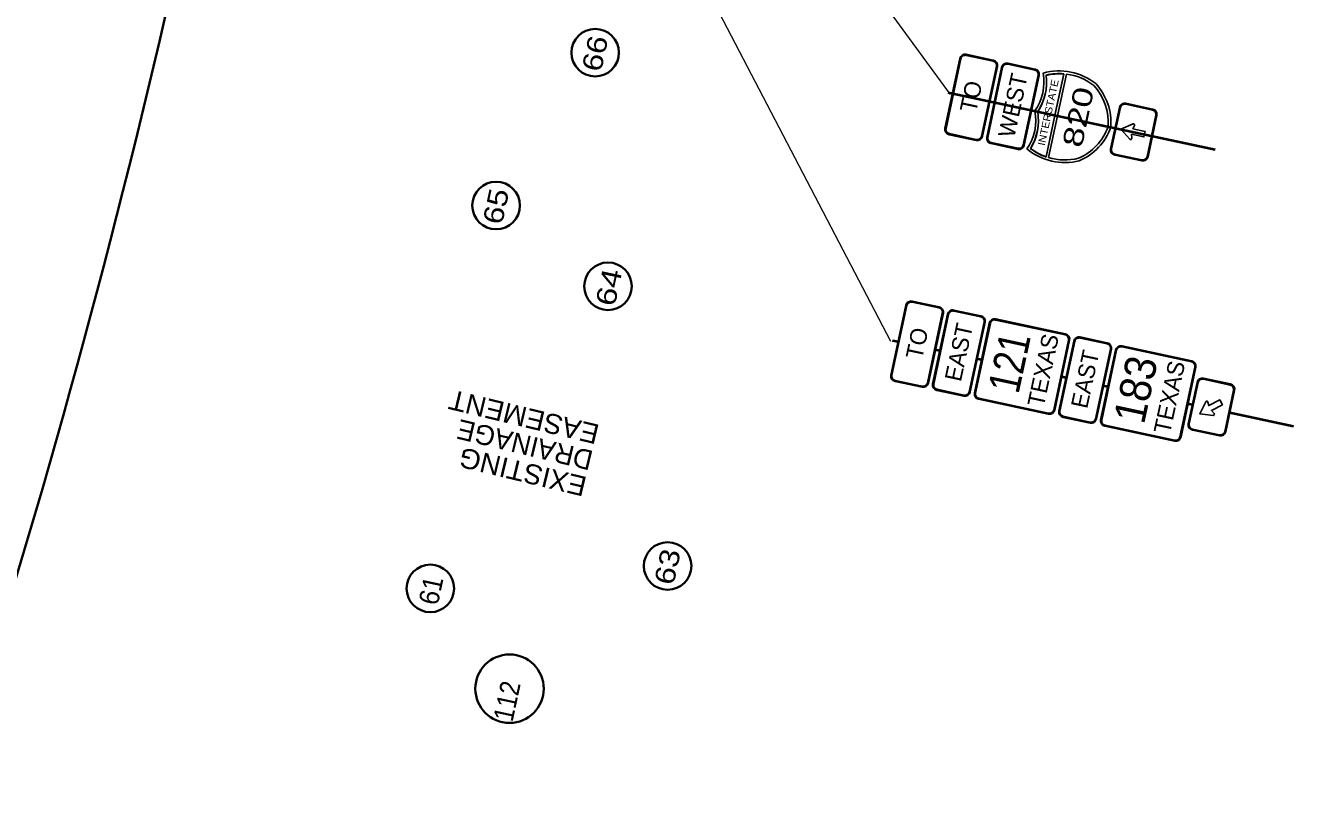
# Model space of a CAD drawing. Extents: x 2363411 to 2369702, y 6977197 to 6988655.
# Drawn here: x 2366110 to 2367007, y 6983011 to 6983553 of the extents above; entities that cross this region are included whole.
import ezdxf
from ezdxf.enums import TextEntityAlignment as Align

# ---------------------------------------------------------------- set-up
doc = ezdxf.new("R2010")
doc.units = 0
doc.header["$LTSCALE"] = 5.6
for name, color, linetype, lineweight in [('1', 7, 'Continuous', 25), ('17', 7, 'Continuous', 35), ('48', 7, 'Continuous', 25), ('55', 7, 'Continuous', 35)]:
    doc.layers.add(name, color=color, linetype=linetype, lineweight=lineweight)

msp = doc.modelspace()

# ---------------------------------------------------------------- linework, layer by layer
at = {"layer": '1', "lineweight": 13}
for p, q in [((2366432.524, 6983885.673), (2366722.178, 6983330.158)), ((2366489.804, 6983881.732), (2366764.313, 6983504.552))]:
    msp.add_line(p, q, dxfattribs=at)
at = {"layer": '1'}
for p, q in [((2366844.762, 6983519.251), (2366838.496, 6983489.913)), ((2366846.653, 6983519.04), (2366840.344, 6983489.521)), ((2366832.229, 6983460.577), (2366838.496, 6983489.913)), ((2366834.036, 6983459.977), (2366840.344, 6983489.521)), ((2366832.255, 6983460.372), (2366832.26, 6983460.382))]:
    msp.add_line(p, q, dxfattribs=at)
for points in [[(2366832.26, 6983460.382), (2366838.524, 6983489.72), (2366844.792, 6983519.049)], [(2366846.653, 6983519.042), (2366840.344, 6983489.521), (2366834.037, 6983459.977)]]:
    msp.add_lwpolyline(points, dxfattribs=at)
at = {"layer": '1', "lineweight": 35}
msp.add_arc((2359877.328, 6985028.058), 6500, 337.9611, 358.49155, dxfattribs=at)
at = {"layer": '1'}
for centre, radius, start, end in [((2366794.792, 6983513.514), 35.984, 325.11936, 9.96967), ((2366794.792, 6983513.514), 37.874, 326.31727, 7.31411), ((2366794.821, 6983513.319), 37.876, 326.31755, 7.31439), ((2366841.448, 6983479.316), 41.954, 51.80216, 105.50453), ((2366841.448, 6983479.316), 40.064, 85.2486, 103.11335), ((2366841.478, 6983479.12), 40.066, 85.25606, 103.11363), ((2366841.446, 6983479.316), 40.066, 52.01897, 82.53095), ((2366841.448, 6983479.316), 40.064, 52.01869, 82.53068), ((2366837.454, 6983484.715), 38.81, 355.77729, 42.42367), ((2366837.456, 6983484.715), 38.808, 355.77701, 42.42339), ((2366837.456, 6983484.715), 40.698, 355.41087, 42.64677), ((2366788.96, 6983486.218), 35.984, 325.90827, 10.75858), ((2366788.96, 6983486.218), 37.874, 328.56383, 9.56067), ((2366788.988, 6983486.023), 37.876, 328.56411, 9.56095), ((2366839.666, 6983495.066), 38.81, 293.45483, 340.10121), ((2366839.668, 6983495.066), 38.808, 293.45455, 340.10093), ((2366839.668, 6983495.066), 40.698, 293.23117, 340.46707), ((2366845.517, 6983498.362), 41.954, 230.37341, 284.07578), ((2366845.517, 6983498.362), 40.064, 232.76459, 250.62934), ((2366845.548, 6983498.167), 40.066, 232.76486, 250.62547), ((2366845.517, 6983498.362), 40.064, 253.34726, 283.85925), ((2366845.516, 6983498.363), 40.066, 253.35167, 283.85953)]:
    msp.add_arc(centre, radius, start, end, dxfattribs=at)
at = {"layer": '17'}
for centre, radius in [((2366513.358, 6983534.192), 16.828), ((2366443.307, 6983426.053), 16.828), ((2366522.427, 6983368.915), 16.828), ((2366564.604, 6983171.066), 16.828), ((2366396.799, 6983155.195), 16.828), ((2366452.783, 6983084.265), 24.19)]:
    msp.add_circle(centre, radius, dxfattribs=at)
at = {"layer": '48'}
for p, q in [((2366760.731, 6983480.729), (2366771.271, 6983530.06)), ((2366761.482, 6983480.569), (2366772.022, 6983529.899)), ((2366761.482, 6983480.569), (2366772.022, 6983529.899)), ((2366775.669, 6983532.262), (2366794.751, 6983528.184)), ((2366775.669, 6983532.262), (2366794.751, 6983528.184)), ((2366775.829, 6983533.013), (2366794.912, 6983528.935)), ((2366805.196, 6983525.953), (2366824.278, 6983521.875)), ((2366805.196, 6983525.953), (2366824.278, 6983521.875)), ((2366805.356, 6983526.704), (2366824.439, 6983522.626)), ((2366797.114, 6983524.538), (2366786.573, 6983475.207)), ((2366797.114, 6983524.538), (2366786.573, 6983475.207)), ((2366797.865, 6983524.378), (2366787.324, 6983475.047)), ((2366790.258, 6983474.42), (2366800.798, 6983523.751)), ((2366791.009, 6983474.26), (2366801.549, 6983523.59)), ((2366791.009, 6983474.26), (2366801.549, 6983523.59)), ((2366826.641, 6983518.229), (2366816.1, 6983468.898)), ((2366826.641, 6983518.229), (2366816.1, 6983468.898)), ((2366827.392, 6983518.069), (2366816.851, 6983468.738)), ((2366877.835, 6983466.219), (2366884.08, 6983495.445)), ((2366878.586, 6983466.058), (2366884.831, 6983495.284)), ((2366878.586, 6983466.058), (2366884.831, 6983495.284)), ((2366888.477, 6983497.647), (2366907.56, 6983493.569)), ((2366888.477, 6983497.647), (2366907.56, 6983493.569)), ((2366888.637, 6983498.398), (2366907.72, 6983494.32)), ((2366909.922, 6983489.923), (2366903.677, 6983460.697)), ((2366909.922, 6983489.923), (2366903.677, 6983460.697)), ((2366910.673, 6983489.763), (2366904.428, 6983460.537)), ((2366782.767, 6983472.094), (2366763.684, 6983476.171)), ((2366782.927, 6983472.845), (2366763.844, 6983476.922)), ((2366782.927, 6983472.845), (2366763.844, 6983476.922)), ((2366812.294, 6983465.785), (2366793.211, 6983469.862)), ((2366812.454, 6983466.536), (2366793.371, 6983470.613)), ((2366812.454, 6983466.536), (2366793.371, 6983470.613)), ((2366899.871, 6983457.584), (2366880.788, 6983461.661)), ((2366900.031, 6983458.335), (2366880.948, 6983462.412)), ((2366900.031, 6983458.335), (2366880.948, 6983462.412)), ((2366722.5, 6983306.15), (2366733.04, 6983355.481)), ((2366723.251, 6983305.99), (2366733.791, 6983355.32)), ((2366723.251, 6983305.99), (2366733.791, 6983355.32)), ((2366737.437, 6983357.683), (2366756.52, 6983353.605)), ((2366737.437, 6983357.683), (2366756.52, 6983353.605)), ((2366737.598, 6983358.434), (2366756.681, 6983354.356)), ((2366758.882, 6983349.959), (2366748.342, 6983300.628)), ((2366758.882, 6983349.959), (2366748.342, 6983300.628)), ((2366759.634, 6983349.799), (2366749.093, 6983300.468)), ((2366752.027, 6983299.841), (2366762.567, 6983349.172)), ((2366752.778, 6983299.681), (2366763.318, 6983349.011)), ((2366752.778, 6983299.681), (2366763.318, 6983349.011)), ((2366766.964, 6983351.374), (2366786.047, 6983347.296)), ((2366766.964, 6983351.374), (2366786.047, 6983347.296)), ((2366767.125, 6983352.125), (2366786.208, 6983348.047)), ((2366788.409, 6983343.65), (2366777.869, 6983294.319)), ((2366788.409, 6983343.65), (2366777.869, 6983294.319)), ((2366789.161, 6983343.49), (2366778.62, 6983294.159)), ((2366781.554, 6983293.532), (2366792.094, 6983342.863)), ((2366782.305, 6983293.372), (2366792.845, 6983342.702)), ((2366782.305, 6983293.372), (2366792.845, 6983342.702)), ((2366796.491, 6983345.065), (2366845.822, 6983334.524)), ((2366796.491, 6983345.065), (2366845.822, 6983334.524)), ((2366796.652, 6983345.816), (2366845.983, 6983335.275)), ((2366848.184, 6983330.878), (2366837.644, 6983281.547)), ((2366848.184, 6983330.878), (2366837.644, 6983281.547)), ((2366848.935, 6983330.718), (2366838.395, 6983281.387)), ((2366841.329, 6983280.76), (2366851.869, 6983330.091)), ((2366842.08, 6983280.6), (2366852.62, 6983329.93)), ((2366842.08, 6983280.6), (2366852.62, 6983329.93)), ((2366856.266, 6983332.293), (2366875.349, 6983328.215)), ((2366856.266, 6983332.293), (2366875.349, 6983328.215)), ((2366856.427, 6983333.044), (2366875.51, 6983328.966)), ((2366877.711, 6983324.569), (2366867.171, 6983275.238)), ((2366877.711, 6983324.569), (2366867.171, 6983275.238)), ((2366878.462, 6983324.409), (2366867.922, 6983275.078)), ((2366870.856, 6983274.451), (2366881.396, 6983323.782)), ((2366871.607, 6983274.291), (2366882.147, 6983323.621)), ((2366871.607, 6983274.291), (2366882.147, 6983323.621)), ((2366885.793, 6983325.984), (2366935.124, 6983315.443)), ((2366885.793, 6983325.984), (2366935.124, 6983315.443)), ((2366885.954, 6983326.735), (2366935.284, 6983316.194)), ((2366937.486, 6983311.797), (2366926.946, 6983262.466)), ((2366937.486, 6983311.797), (2366926.946, 6983262.466)), ((2366938.237, 6983311.637), (2366927.697, 6983262.306)), ((2366744.535, 6983297.515), (2366725.453, 6983301.593)), ((2366744.696, 6983298.266), (2366725.613, 6983302.344)), ((2366744.696, 6983298.266), (2366725.613, 6983302.344)), ((2366943.42, 6983303.159), (2366962.503, 6983299.082)), ((2366943.42, 6983303.159), (2366962.503, 6983299.082)), ((2366943.581, 6983303.91), (2366962.664, 6983299.833)), ((2366774.062, 6983291.206), (2366754.98, 6983295.284)), ((2366774.223, 6983291.957), (2366755.14, 6983296.035)), ((2366774.223, 6983291.957), (2366755.14, 6983296.035)), ((2366932.779, 6983271.732), (2366939.023, 6983300.957)), ((2366933.53, 6983271.571), (2366939.774, 6983300.797)), ((2366933.53, 6983271.571), (2366939.774, 6983300.797)), ((2366964.865, 6983295.436), (2366958.621, 6983266.21)), ((2366964.865, 6983295.436), (2366958.621, 6983266.21)), ((2366965.616, 6983295.275), (2366959.372, 6983266.049)), ((2366833.837, 6983278.434), (2366784.507, 6983288.975)), ((2366833.998, 6983279.185), (2366784.667, 6983289.726)), ((2366833.998, 6983279.185), (2366784.667, 6983289.726)), ((2366863.364, 6983272.125), (2366844.282, 6983276.203)), ((2366863.525, 6983272.876), (2366844.442, 6983276.954)), ((2366863.525, 6983272.876), (2366844.442, 6983276.954)), ((2366923.139, 6983259.353), (2366873.809, 6983269.894)), ((2366923.3, 6983260.104), (2366873.969, 6983270.645)), ((2366923.3, 6983260.104), (2366873.969, 6983270.645)), ((2366954.814, 6983263.097), (2366935.731, 6983267.174)), ((2366954.975, 6983263.848), (2366935.892, 6983267.925)), ((2366954.975, 6983263.848), (2366935.892, 6983267.925))]:
    msp.add_line(p, q, dxfattribs=at)
at = {"layer": '48', "lineweight": 40}
for p, q in [((2366762.962, 6983506.044), (2366951.956, 6983465.662)), ((2366723.531, 6983330.659), (2366727.603, 6983329.789)), ((2366753.909, 6983324.168), (2366757.015, 6983323.504)), ((2366783.321, 6983317.883), (2366786.427, 6983317.22)), ((2366843.3, 6983305.068), (2366846.211, 6983304.446)), ((2366872.743, 6983298.777), (2366875.752, 6983298.134)), ((2366932.555, 6983285.997), (2366935.661, 6983285.333)), ((2366962.257, 6983279.65), (2367007.333, 6983270.019))]:
    msp.add_line(p, q, dxfattribs=at)
at = {"layer": '48'}
for points in [[(2366891.562, 6983473.044), (2366885.078, 6983480.025), (2366893.771, 6983483.726)], [(2366894.762, 6983482.681), (2366893.619, 6983480.372), (2366902.273, 6983478.523), (2366901.429, 6983474.567), (2366892.774, 6983476.417), (2366892.906, 6983473.592)], [(2366950.409, 6983277.621), (2366940.955, 6983278.801), (2366945.235, 6983287.223)], [(2366946.666, 6983287.06), (2366947.274, 6983284.556), (2366955.093, 6983288.703), (2366956.989, 6983285.13), (2366949.169, 6983280.984), (2366951.087, 6983278.905)]]:
    msp.add_lwpolyline(points, dxfattribs=at)
for centre, radius, start, end in [((2366775.027, 6983529.257), 3.84, 77.93906, 167.93906), ((2366775.027, 6983529.257), 3.072, 77.93906, 167.93906), ((2366775.027, 6983529.257), 3.072, 77.93906, 167.93906), ((2366794.109, 6983525.18), 3.072, 347.93906, 77.93906), ((2366794.109, 6983525.18), 3.072, 347.93906, 77.93906), ((2366794.109, 6983525.18), 3.84, 347.93906, 77.93906), ((2366804.554, 6983522.948), 3.84, 77.93906, 167.93906), ((2366804.554, 6983522.948), 3.072, 77.93906, 167.93906), ((2366804.554, 6983522.948), 3.072, 77.93906, 167.93906), ((2366823.636, 6983518.871), 3.072, 347.93906, 77.93906), ((2366823.636, 6983518.871), 3.072, 347.93906, 77.93906), ((2366823.636, 6983518.871), 3.84, 347.93906, 77.93906), ((2366887.835, 6983494.642), 3.84, 77.93906, 167.93906), ((2366887.835, 6983494.642), 3.072, 77.93906, 167.93906), ((2366887.835, 6983494.642), 3.072, 77.93906, 167.93906), ((2366906.918, 6983490.565), 3.072, 347.93906, 77.93906), ((2366906.918, 6983490.565), 3.072, 347.93906, 77.93906), ((2366906.918, 6983490.565), 3.84, 347.93906, 77.93906), ((2366894.074, 6983483.02), 0.767, 333.43756, 113.07618), ((2366764.486, 6983479.927), 3.84, 167.93906, 257.93906), ((2366764.486, 6983479.927), 3.072, 167.93906, 257.93906), ((2366764.486, 6983479.927), 3.072, 167.93906, 257.93906), ((2366783.569, 6983475.849), 3.84, 257.93906, 347.93906), ((2366783.569, 6983475.849), 3.072, 257.93906, 347.93906), ((2366783.569, 6983475.849), 3.072, 257.93906, 347.93906), ((2366794.013, 6983473.618), 3.84, 167.93906, 257.93906), ((2366794.013, 6983473.618), 3.072, 167.93906, 257.93906), ((2366794.013, 6983473.618), 3.072, 167.93906, 257.93906), ((2366892.131, 6983473.559), 0.767, 222.92454, 2.65311), ((2366813.096, 6983469.54), 3.84, 257.93906, 347.93906), ((2366813.096, 6983469.54), 3.072, 257.93906, 347.93906), ((2366813.096, 6983469.54), 3.072, 257.93906, 347.93906), ((2366881.59, 6983465.417), 3.84, 167.93906, 257.93906), ((2366881.59, 6983465.417), 3.072, 167.93906, 257.93906), ((2366881.59, 6983465.417), 3.072, 167.93906, 257.93906), ((2366900.673, 6983461.339), 3.84, 257.93906, 347.93906), ((2366900.673, 6983461.339), 3.072, 257.93906, 347.93906), ((2366900.673, 6983461.339), 3.072, 257.93906, 347.93906), ((2366736.796, 6983354.678), 3.84, 77.93906, 167.93906), ((2366736.796, 6983354.678), 3.072, 77.93906, 167.93906), ((2366736.796, 6983354.678), 3.072, 77.93906, 167.93906), ((2366755.878, 6983350.601), 3.072, 347.93906, 77.93906), ((2366755.878, 6983350.601), 3.072, 347.93906, 77.93906), ((2366755.878, 6983350.601), 3.84, 347.93906, 77.93906), ((2366766.323, 6983348.369), 3.84, 77.93906, 167.93906), ((2366766.323, 6983348.369), 3.072, 77.93906, 167.93906), ((2366766.323, 6983348.369), 3.072, 77.93906, 167.93906), ((2366785.405, 6983344.292), 3.072, 347.93906, 77.93906), ((2366785.405, 6983344.292), 3.072, 347.93906, 77.93906), ((2366785.405, 6983344.292), 3.84, 347.93906, 77.93906), ((2366795.85, 6983342.06), 3.84, 77.93906, 167.93906), ((2366795.85, 6983342.06), 3.072, 77.93906, 167.93906), ((2366795.85, 6983342.06), 3.072, 77.93906, 167.93906), ((2366845.18, 6983331.52), 3.072, 347.93906, 77.93906), ((2366845.18, 6983331.52), 3.072, 347.93906, 77.93906), ((2366845.18, 6983331.52), 3.84, 347.93906, 77.93906), ((2366855.624, 6983329.288), 3.84, 77.93906, 167.93906), ((2366855.624, 6983329.288), 3.072, 77.93906, 167.93906), ((2366855.624, 6983329.288), 3.072, 77.93906, 167.93906), ((2366874.707, 6983325.211), 3.84, 347.93906, 77.93906), ((2366874.707, 6983325.211), 3.072, 347.93906, 77.93906), ((2366874.707, 6983325.211), 3.072, 347.93906, 77.93906), ((2366885.151, 6983322.979), 3.84, 77.93906, 167.93906), ((2366885.151, 6983322.979), 3.072, 77.93906, 167.93906), ((2366885.151, 6983322.979), 3.072, 77.93906, 167.93906), ((2366934.482, 6983312.439), 3.072, 347.93906, 77.93906), ((2366934.482, 6983312.439), 3.072, 347.93906, 77.93906), ((2366934.482, 6983312.439), 3.84, 347.93906, 77.93906), ((2366726.255, 6983305.348), 3.84, 167.93906, 257.93906), ((2366726.255, 6983305.348), 3.072, 167.93906, 257.93906), ((2366726.255, 6983305.348), 3.072, 167.93906, 257.93906), ((2366942.778, 6983300.155), 3.84, 77.93906, 167.93906), ((2366942.778, 6983300.155), 3.072, 77.93906, 167.93906), ((2366942.778, 6983300.155), 3.072, 77.93906, 167.93906), ((2366745.338, 6983301.27), 3.84, 257.93906, 347.93906), ((2366745.338, 6983301.27), 3.072, 257.93906, 347.93906), ((2366745.338, 6983301.27), 3.072, 257.93906, 347.93906), ((2366755.782, 6983299.039), 3.84, 167.93906, 257.93906), ((2366755.782, 6983299.039), 3.072, 167.93906, 257.93906), ((2366755.782, 6983299.039), 3.072, 167.93906, 257.93906), ((2366774.865, 6983294.961), 3.84, 257.93906, 347.93906), ((2366774.865, 6983294.961), 3.072, 257.93906, 347.93906), ((2366774.865, 6983294.961), 3.072, 257.93906, 347.93906), ((2366785.309, 6983292.73), 3.84, 167.93906, 257.93906), ((2366785.309, 6983292.73), 3.072, 167.93906, 257.93906), ((2366785.309, 6983292.73), 3.072, 167.93906, 257.93906), ((2366961.861, 6983296.078), 3.072, 347.93906, 77.93906), ((2366961.861, 6983296.078), 3.072, 347.93906, 77.93906), ((2366961.861, 6983296.078), 3.84, 347.93906, 77.93906), ((2366945.92, 6983286.878), 0.767, 13.43756, 153.07618), ((2366834.64, 6983282.189), 3.84, 257.93906, 347.93906), ((2366834.64, 6983282.189), 3.072, 257.93906, 347.93906), ((2366834.64, 6983282.189), 3.072, 257.93906, 347.93906), ((2366845.084, 6983279.958), 3.84, 167.93906, 257.93906), ((2366845.084, 6983279.958), 3.072, 167.93906, 257.93906), ((2366845.084, 6983279.958), 3.072, 167.93906, 257.93906), ((2366864.167, 6983275.88), 3.84, 257.93906, 347.93906), ((2366864.167, 6983275.88), 3.072, 257.93906, 347.93906), ((2366864.167, 6983275.88), 3.072, 257.93906, 347.93906), ((2366950.513, 6983278.382), 0.767, 262.92454, 42.65311), ((2366874.611, 6983273.649), 3.84, 167.93906, 257.93906), ((2366874.611, 6983273.649), 3.072, 167.93906, 257.93906), ((2366874.611, 6983273.649), 3.072, 167.93906, 257.93906), ((2366936.534, 6983270.929), 3.84, 167.93906, 257.93906), ((2366936.534, 6983270.929), 3.072, 167.93906, 257.93906), ((2366936.534, 6983270.929), 3.072, 167.93906, 257.93906), ((2366955.617, 6983266.852), 3.84, 257.93906, 347.93906), ((2366955.617, 6983266.852), 3.072, 257.93906, 347.93906), ((2366955.617, 6983266.852), 3.072, 257.93906, 347.93906), ((2366923.942, 6983263.108), 3.84, 257.93906, 347.93906), ((2366923.942, 6983263.108), 3.072, 257.93906, 347.93906), ((2366923.942, 6983263.108), 3.072, 257.93906, 347.93906)]:
    msp.add_arc(centre, radius, start, end, dxfattribs=at)

# ---------------------------------------------------------------- texts
at = {"layer": '1'}
for s, height, width, p in [('INTERSTATE', 5.198, 1.1, (2366831.348, 6983468.05)), ('820', 14.18, 1.35, (2366857.417, 6983466.3))]:
    msp.add_text(s, height=height, rotation=77.939, dxfattribs=dict(at, width=width)).set_placement(p)
at = {"layer": '17'}
for s, width, p in [('66', 1.2, (2366520.091, 6983532.204)), ('65', 1.2, (2366450.039, 6983424.066)), ('64', 1.25, (2366529.859, 6983366.779)), ('63', 1.2, (2366571.337, 6983169.079)), ('61', 0.95, (2366404.069, 6983152.305)), ('112', 0.9, (2366457.835, 6983074.017))]:
    msp.add_text(s, height=14, rotation=77.939, dxfattribs=dict(at, width=width)).set_placement(p, align=Align.CENTER)
at = {"layer": '48'}
for s, p in [('WEST', (2366814.537, 6983495.651)), ('TO', (2366785.01, 6983501.96)), ('TO', (2366746.781, 6983327.38)), ('EAST', (2366776.307, 6983321.071)), ('TEXAS', (2366835.971, 6983308.322)), ('EAST', (2366865.609, 6983301.989)), ('TEXAS', (2366925.272, 6983289.241))]:
    msp.add_text(s, height=11.82, rotation=77.859, dxfattribs=at).set_placement(p, align=Align.CENTER)
for s, width, p in [('121', 0.85, (2366817.13, 6983312.676)), ('183', 0.95, (2366906.431, 6983293.596))]:
    msp.add_text(s, height=22.16, rotation=77.859, dxfattribs=dict(at, width=width)).set_placement(p, align=Align.CENTER)
at = {"layer": '55', "width": 1.05}
for s, p in [('EASEMENT', (2366517.222, 6983270.65)), ('EXISTING', (2366508.339, 6983233.701))]:
    msp.add_text(s, height=14, rotation=166.482, dxfattribs=at).set_placement(p)
at = {"layer": '55'}
msp.add_text('DRAINAGE', height=14, rotation=166.482, dxfattribs=at).set_placement((2366512.78, 6983252.175))

doc.saveas('drawing.dxf')
